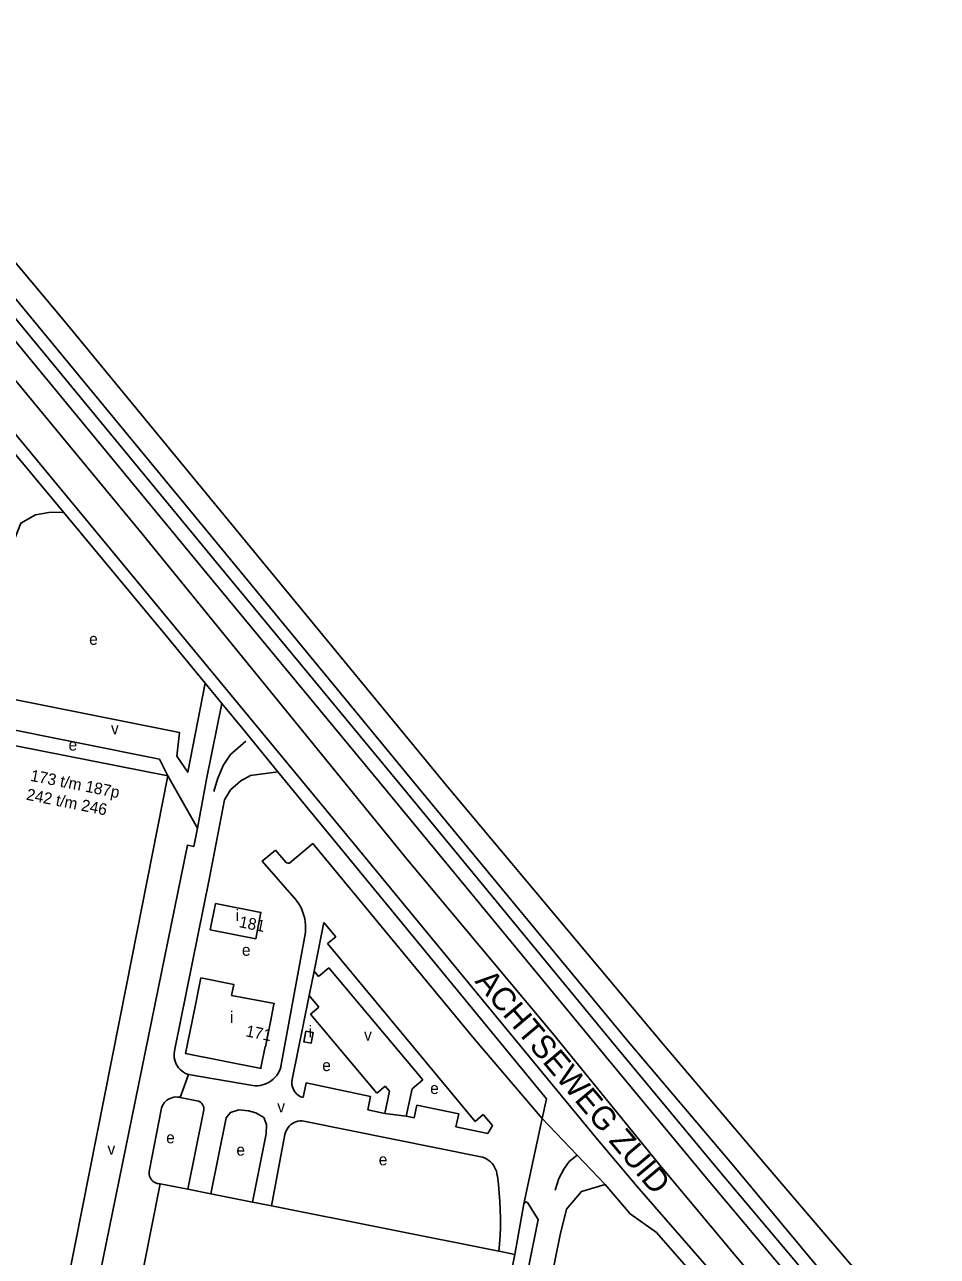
# Model space of a CAD drawing. Extents: x 158356 to 159894, y 383831 to 385260.
# Drawn here: x 159379.2 to 159694.7, y 384819.2 to 385244.9 of the extents above; entities that cross this region are included whole.
import ezdxf

# ---------------------------------------------------------------- set-up
doc = ezdxf.new("R2010")
doc.units = 0
for name, color, linetype in [('BLT_Basislijn', 7, 'Continuous'), ('BLT_Bebouwing', 7, 'Continuous'), ('BLT_Centroide', 7, 'Continuous'), ('BLT_Huisnummer', 7, 'Continuous'), ('BLT_Huisnummer_reeks', 7, 'Continuous'), ('BLT_Spoorlijn', 7, 'Continuous'), ('BLT_Straatnaam_hoofdweg', 7, 'Continuous'), ('BLT_Vlakafsluiter', 7, 'Continuous')]:
    doc.layers.add(name, color=color, linetype=linetype)

msp = doc.modelspace()

# ---------------------------------------------------------------- linework, layer by layer
at = {"layer": 'BLT_Basislijn'}
for p, q in [((159363.27, 385137.29), (159419.79, 385068.91)), ((159371.04, 385102.42), (159392.7, 385076.35)), ((159419.79, 385068.91), (159511.57, 384956.24)), ((159441.6, 385017.31), (159447.43, 385010.21)), ((159447.43, 385010.21), (159454.6, 385001.47)), ((159454.6, 385001.47), (159466.79, 384986.61)), ((159428.71, 384985.2), (159438.93, 384967.17)), ((159466.79, 384986.61), (159559.56, 384873.58)), ((159431.17, 384890.76), (159443.07, 384950)), ((159482.65, 384934.58), (159479.25, 384917.76)), ((159482.65, 384934.58), (159486.81, 384929.64)), ((159483.95, 384927.26), (159486.81, 384929.64)), ((159475.97, 384929.31), (159467.82, 384884.8)), ((159534.9, 384865.81), (159483.95, 384927.26)), ((159479.25, 384917.76), (159477.54, 384909.34)), ((159479.25, 384917.76), (159480.83, 384915.88)), ((159480.83, 384915.88), (159484.4, 384918.84)), ((159484.4, 384918.84), (159516.9, 384880.23)), ((159471.66, 384880.31), (159477.54, 384909.34)), ((159477.54, 384909.34), (159480.91, 384905.33)), ((159477.98, 384902.9), (159480.91, 384905.33)), ((159477.98, 384902.9), (159500.95, 384875.61)), ((159561.66, 384896.37), (159599.4, 384850.02)), ((159458.11, 384878.22), (159435.87, 384881.98)), ((159476.56, 384879.1), (159475.49, 384874.08)), ((159476.56, 384879.1), (159498.83, 384874.37)), ((159513.15, 384877.12), (159516.9, 384880.23)), ((159432.99, 384874.11), (159438.79, 384872.98)), ((159498.83, 384874.37), (159497.87, 384869.85)), ((159500.95, 384875.61), (159503.88, 384878.04)), ((159505.39, 384876.25), (159503.76, 384868.6)), ((159503.88, 384878.04), (159505.39, 384876.25)), ((159513.15, 384877.12), (159511.14, 384867.65)), ((159426.38, 384869.8), (159422.4, 384849.09)), ((159497.87, 384869.85), (159503.76, 384868.6)), ((159514.84, 384871.45), (159513.91, 384867.06)), ((159514.84, 384871.45), (159529.26, 384868.39)), ((159558.15, 384866.84), (159559.56, 384873.58)), ((159441.08, 384869.21), (159435.6, 384842.36)), ((159476.3, 384865.81), (159536.9, 384853.61)), ((159511.14, 384867.65), (159503.76, 384868.6)), ((159511.14, 384867.65), (159513.91, 384867.06)), ((159529.26, 384868.39), (159528.33, 384863.99)), ((159534.9, 384865.81), (159537.77, 384868.19)), ((159537.77, 384868.19), (159540.96, 384864.4)), ((159551.75, 384837.34), (159558.15, 384866.84)), ((159570.22, 384854.16), (159558.15, 384866.84)), ((159469.21, 384861.28), (159464.57, 384836.6)), ((159528.33, 384863.99), (159539.38, 384861.64)), ((159539.38, 384861.64), (159540.96, 384864.4)), ((159579.93, 384843.97), (159570.22, 384854.16)), ((159599.4, 384850.02), (159634.55, 384807.95)), ((159590.89, 384843.45), (159658.67, 384765.63)), ((159548.66, 384819.86), (159551.75, 384837.34))]:
    msp.add_line(p, q, dxfattribs=at)
for points in [[(159284.81, 385244.88), (159371.58, 385140.86), (159441.69, 385055.79)], [(159265.25, 385221.46), (159278.38, 385212.98), (159295.33, 385199.25), (159308.05, 385185.51), (159369.78, 385110.67), (159492.78, 384962.08), (159563.22, 384876.56)], [(159375.44, 385144.04), (159445.55, 385058.97)], [(159365.17, 385013.71), (159375.78, 385067.3), (159377.95, 385072.59), (159383.02, 385075.45), (159387.63, 385076.25), (159392.7, 385076.35)], [(159392.7, 385076.35), (159428.29, 385033.53), (159441.6, 385017.31)], [(159441.69, 385055.79), (159504.62, 384979.74), (159579.89, 384888.43)], [(159365.17, 385013.71), (159432.72, 385000.28), (159431.79, 384992.1), (159435.6, 384986.48), (159441.6, 385017.31)], [(159438.93, 384967.17), (159442.22, 384984.62), (159447.43, 385010.21)], [(159368.31, 385002.52), (159425.83, 384991), (159428.71, 384985.2)], [(159455.72, 384997.22), (159450.36, 384992.63), (159447.85, 384988.88), (159445.85, 384984.09), (159444.62, 384979.88)], [(159443.07, 384950), (159448.33, 384976.94), (159450.33, 384980.36), (159453.9, 384983.57), (159457.31, 384985.32), (159466.79, 384986.61)], [(159438.93, 384967.17), (159437.75, 384960.87), (159435.49, 384961.29), (159381.53, 384696.68)], [(159465.94, 384959.6), (159461.37, 384955.78), (159473.15, 384942.16)], [(159465.94, 384959.6), (159469.5, 384955.41), (159469.85, 384955.13), (159470.27, 384955.02), (159470.71, 384955.11), (159470.91, 384955.24), (159478.79, 384961.81)], [(159478.79, 384961.81), (159534.67, 384894.28), (159558.15, 384866.84)], [(159511.57, 384956.24), (159561.66, 384896.37)], [(159475.97, 384929.31), (159476.18, 384930.4), (159476.31, 384931.5), (159476.36, 384932.61), (159476.33, 384933.72), (159476.22, 384934.82), (159476.04, 384935.91), (159475.77, 384936.99), (159475.43, 384938.05), (159475.01, 384939.07), (159474.52, 384940.07), (159473.95, 384941.02), (159473.32, 384941.93), (159473.15, 384942.16)], [(159431.17, 384890.76), (159431, 384890.02), (159430.91, 384889.27), (159430.9, 384888.51), (159430.96, 384887.76), (159431.11, 384887.02), (159431.34, 384886.3), (159431.64, 384885.61), (159432.01, 384884.95), (159432.45, 384884.33), (159432.95, 384883.77), (159433.51, 384883.26), (159434.12, 384882.81), (159434.77, 384882.43), (159435.46, 384882.12), (159435.87, 384881.98)], [(159579.89, 384888.43), (159615.45, 384845.5), (159670.94, 384779.64)], [(159458.11, 384878.22), (159458.95, 384878.15), (159459.79, 384878.16), (159460.63, 384878.26), (159461.45, 384878.43), (159462.26, 384878.68), (159463.03, 384879), (159463.78, 384879.39), (159464.48, 384879.86), (159465.13, 384880.39), (159465.73, 384880.98), (159466.28, 384881.62), (159466.76, 384882.31), (159467.17, 384883.05), (159467.51, 384883.82), (159467.77, 384884.61), (159467.82, 384884.8)], [(159471.66, 384880.31), (159471.55, 384879.48), (159471.58, 384878.6), (159471.76, 384877.71), (159472.1, 384876.84), (159472.59, 384876.04), (159473.22, 384875.34), (159473.93, 384874.78), (159474.7, 384874.36), (159475.49, 384874.08)], [(159426.38, 384869.8), (159426.53, 384870.43), (159426.76, 384871.05), (159427.06, 384871.64), (159427.43, 384872.18), (159427.87, 384872.67), (159428.36, 384873.11), (159428.9, 384873.48), (159429.49, 384873.79), (159430.1, 384874.02), (159430.74, 384874.18), (159431.39, 384874.26), (159432.05, 384874.25), (159432.7, 384874.17), (159432.99, 384874.11)], [(159563.22, 384876.56), (159576.67, 384860.23), (159590.89, 384843.45)], [(159438.79, 384872.98), (159439.26, 384872.85), (159439.7, 384872.64), (159440.1, 384872.36), (159440.46, 384872.02), (159440.75, 384871.63), (159440.97, 384871.19), (159441.12, 384870.73), (159441.19, 384870.25), (159441.19, 384869.76), (159441.08, 384869.21)], [(159443.63, 384840.76), (159448.87, 384867.08), (159450.36, 384868.9), (159453.28, 384869.85), (159456.58, 384869.42), (159459.08, 384868.79), (159461.86, 384867.15), (159462.8, 384864.8), (159462.7, 384861.5), (159457.98, 384837.91)], [(159469.21, 384861.28), (159469.37, 384861.93), (159469.61, 384862.57), (159469.92, 384863.17), (159470.3, 384863.73), (159470.74, 384864.25), (159471.23, 384864.71), (159471.78, 384865.1), (159472.38, 384865.43), (159473, 384865.69), (159473.65, 384865.87), (159474.32, 384865.97), (159475, 384866), (159475.68, 384865.94), (159476.3, 384865.81)], [(159536.9, 384853.61), (159537.64, 384853.4), (159538.36, 384853.11), (159539.04, 384852.75), (159539.67, 384852.32), (159540.27, 384851.83), (159540.8, 384851.28), (159541.28, 384850.67), (159541.69, 384850.02), (159542.03, 384849.34), (159542.3, 384848.61), (159542.49, 384847.87), (159542.6, 384847.11), (159542.62, 384846.92)], [(159562.61, 384842), (159563.88, 384846.06), (159565.59, 384849.33), (159567.48, 384851.93), (159570.22, 384854.16)], [(159426.12, 384844.25), (159425.57, 384844.27), (159425.03, 384844.37), (159424.51, 384844.55), (159424.03, 384844.8), (159423.58, 384845.12), (159423.19, 384845.5), (159422.86, 384845.93), (159422.59, 384846.41), (159422.39, 384846.93), (159422.27, 384847.46), (159422.24, 384848.01), (159422.28, 384848.55), (159422.4, 384849.09)], [(159542.62, 384846.92), (159542.99, 384844), (159543.29, 384841.07), (159543.51, 384838.14), (159543.65, 384835.2), (159543.7, 384832.26), (159543.68, 384829.31), (159543.58, 384826.37), (159543.4, 384823.43), (159543.18, 384820.95)], [(159579.93, 384843.97), (159571.7, 384841.59), (159566.54, 384835.45), (159564.31, 384826.63), (159554.98, 384780.49)], [(159656.42, 384760.21), (159597.62, 384827.42), (159588.53, 384833.9), (159579.93, 384843.97)], [(159551.75, 384837.34), (159552.37, 384837.98), (159553.02, 384837.75), (159556.78, 384831.86), (159546.06, 384778.64), (159544.8, 384776.49), (159542.76, 384775.45), (159541.27, 384775.17), (159539.91, 384775.41)]]:
    msp.add_lwpolyline(points, dxfattribs=at)
at = {"layer": 'BLT_Bebouwing'}
for p, q in [((159443.39, 384932.02), (159445.2, 384941.16)), ((159426.12, 384844.25), (159435.6, 384842.36)), ((159435.6, 384842.36), (159443.63, 384840.76)), ((159443.63, 384840.76), (159457.98, 384837.91)), ((159457.98, 384837.91), (159459.3, 384837.65)), ((159459.3, 384837.65), (159464.57, 384836.6)), ((159464.57, 384836.6), (159543.18, 384820.95)), ((159548.66, 384819.86), (159540.57, 384779.03)), ((159543.18, 384820.95), (159543.27, 384820.93)), ((159543.27, 384820.93), (159548.66, 384819.86))]:
    msp.add_line(p, q, dxfattribs=at)
for points in [[(159428.71, 384985.2), (159367.28, 384997.32), (159367.81, 385000), (159368.31, 385002.52)], [(159376.06, 384719.31), (159414.39, 384912.96), (159428.71, 384985.2)], [(159445.2, 384941.16), (159460.9, 384938.05), (159459.13, 384928.95), (159443.39, 384932.02)], [(159464.2, 384900.27), (159462.5, 384891.64), (159462.39, 384891.66), (159460.89, 384884.35), (159460.95, 384884.12), (159434.87, 384889.27), (159437.99, 384904.37), (159440.07, 384915.39)], [(159440.07, 384915.39), (159451.5, 384913.16), (159450.77, 384909.37), (159465.56, 384906.55), (159465.41, 384906.38), (159464.2, 384900.27)], [(159476.47, 384897.03), (159478.96, 384896.54), (159478.22, 384892.83), (159475.72, 384893.33), (159476.47, 384897.03)], [(159417.89, 384802.95), (159426.12, 384844.25)]]:
    msp.add_lwpolyline(points, dxfattribs=at)
at = {"layer": 'BLT_Spoorlijn'}
for points in [[(159342.32, 385190.97), (159382.25, 385142.57)], [(159353.54, 385189.31), (159392.37, 385143.12)], [(159382.25, 385142.57), (159451.99, 385058.05)], [(159392.37, 385143.12), (159463.03, 385057.31)], [(159445.55, 385058.97), (159508.48, 384982.92)], [(159451.99, 385058.05), (159513.08, 384983.84)], [(159463.03, 385057.31), (159525.6, 384981.26)], [(159508.48, 384982.92), (159583.75, 384891.61)], [(159513.08, 384983.84), (159587.8, 384893.45)], [(159525.6, 384981.26), (159599.95, 384892.53)], [(159583.75, 384891.61), (159619.27, 384848.73)], [(159587.8, 384893.45), (159624.43, 384850.38)], [(159599.95, 384892.53), (159636.94, 384848.91)], [(159619.27, 384848.73), (159687.56, 384767.69)], [(159624.43, 384850.38), (159694.73, 384765.66)], [(159636.94, 384848.91), (159678.22, 384800.74)]]:
    msp.add_lwpolyline(points, dxfattribs=at)
at = {"layer": 'BLT_Vlakafsluiter'}
msp.add_line((159432.99, 384874.11), (159435.87, 384881.98), dxfattribs=at)

# ---------------------------------------------------------------- texts
at = {"layer": 'BLT_Centroide'}
for s, p in [('e', (159401.52, 385030.54)), ('e', (159394.38, 384994)), ('i', (159452.15, 384935.06)), ('e', (159454.33, 384923.06)), ('i', (159450.22, 384899.83)), ('i', (159477.34, 384894.92)), ('v', (159496.56, 384893.73)), ('e', (159482.09, 384883.21)), ('e', (159519.41, 384875.28)), ('e', (159428.14, 384858.24)), ('e', (159452.42, 384853.98)), ('e', (159501.63, 384850.64))]:
    msp.add_text(s, height=4, dxfattribs=at).set_placement(p)
for p in [(159409.11, 384999.62), (159466.59, 384868.94), (159407.89, 384854.32)]:
    msp.add_text('v', height=4, rotation=1, dxfattribs=at).set_placement(p)
at = {"layer": 'BLT_Huisnummer'}
for s, p in [('181', (159453.11, 384932.98)), ('171', (159455.43, 384895.25))]:
    msp.add_text(s, height=4, rotation=348.8063, dxfattribs=at).set_placement(p)
at = {"layer": 'BLT_Huisnummer_reeks'}
for s, p in [('173 t/m 187p', (159380.99, 384983.56)), ('242 t/m 246', (159379.56, 384977.02))]:
    msp.add_text(s, height=4, rotation=348.8063, dxfattribs=at).set_placement(p)
at = {"layer": 'BLT_Straatnaam_hoofdweg'}
msp.add_text('ACHTSEWEG ZUID', height=8, rotation=310.056, dxfattribs=at).set_placement((159534.61, 384914.11))

doc.saveas('drawing.dxf')
